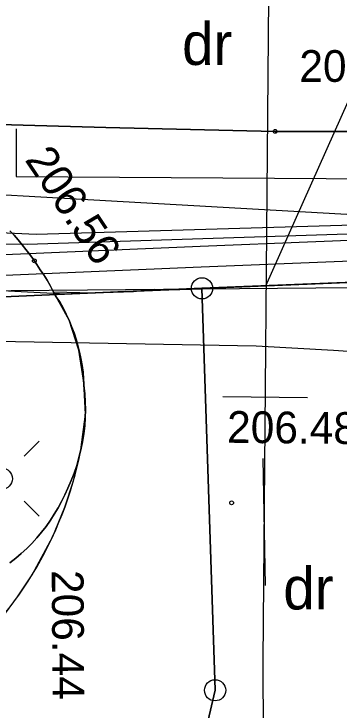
# Model space of a CAD drawing. Extents: x 6512606 to 6513006, y 6022524 to 6022728.
# Drawn here: x 6512731.32 to 6512739, y 6022662.97 to 6022679.43 of the extents above; entities that cross this region are included whole.
import ezdxf

# ---------------------------------------------------------------- set-up
doc = ezdxf.new("R2010")
doc.units = 0
for name, color, linetype in [('202-punkt graniczny', 7, 'Continuous'), ('210-oznaczenie konturu użytku gruntowego', 7, 'Continuous'), ('216-obręb ewidencyjny', 7, 'Continuous'), ('218-kontur użytku gruntowego', 7, 'Continuous'), ('219-działka ewidencyjna', 7, 'Continuous'), ('4', 7, 'Continuous'), ('chodnik (powierzchnia)', 7, 'Continuous'), ('Default', 7, 'Continuous'), ('jezdnia (powierzchnia)', 7, 'Continuous'), ('kolor_kostka_bet', 7, 'Continuous'), ('krawężnik (linia)', 7, 'Continuous'), ('latarnia (punkt)', 7, 'Continuous'), ('Level 60', 7, 'Continuous'), ('maxp_kan_deszczowa', 7, 'Continuous'), ('maxp_kraw_nawierzchni', 7, 'Continuous'), ('maxp_opisy', 7, 'Continuous'), ('maxp_opornik', 7, 'Continuous'), ('maxp_os', 7, 'Continuous'), ('maxp_ramka_2', 7, 'Continuous'), ('przewód elektroenergetyczny (linia)', 7, 'Continuous'), ('przewód elektroenergetyczny niskiego napięcia (linia)', 7, 'Continuous'), ('przewód kanalizacyjny (linia)', 7, 'Continuous'), ('przewód wodociągowy (linia)', 7, 'Continuous'), ('punkt wysokościowy sztuczny', 7, 'Continuous'), ('punkt wysokościowy sztuczny-Atr2', 7, 'Continuous')]:
    doc.layers.add(name, color=color, linetype=linetype)

# ---------------------------------------------------------------- blocks, each defined once
blk = doc.blocks.new('202')
at = {"layer": 'Default'}
blk.add_circle((0, 0), 2.5, dxfattribs=at)
blk = doc.blocks.new('PW02')
at = {"layer": 'Default'}
blk.add_circle((0, 0), 0.45, dxfattribs=at)
blk = doc.blocks.new('SM01')
at = {"layer": 'Default'}
for p, q in [((-5.3, 5.31), (-8.83, 8.84)), ((5.31, 5.31), (8.84, 8.84)), ((-5.3, -5.3), (-8.83, -8.83)), ((5.31, -5.3), (8.84, -8.83))]:
    blk.add_line(p, q, dxfattribs=at)
blk.add_circle((0, 0), 2.5, dxfattribs=at)

msp = doc.modelspace()

# ---------------------------------------------------------------- linework, layer by layer
at = {"layer": '216-obręb ewidencyjny'}
for points in [[(6512688.62, 6022674.91), (6512702.58, 6022674.18), (6512725.78, 6022672.95), (6512730.35, 6022672.71), (6512735.76, 6022672.94), (6512745.51, 6022673.33), (6512754.87, 6022673.72), (6512768.24, 6022674.27), (6512785.56, 6022674.74), (6512790.49, 6022674.74), (6512796.96, 6022674.74), (6512801.96, 6022670.34), (6512828.67, 6022670.98), (6512833.61, 6022675.02), (6512836.69, 6022675.17), (6512851.94, 6022675.93)], [(6512852.25, 6022608.25), (6512838.47, 6022634.29), (6512825.37, 6022649.66), (6512810.18, 6022663.28), (6512801.96, 6022670.34), (6512796.96, 6022674.74), (6512790.49, 6022674.74), (6512785.56, 6022674.74), (6512768.24, 6022674.27), (6512754.87, 6022673.72), (6512745.51, 6022673.33), (6512735.76, 6022672.94), (6512730.35, 6022672.71), (6512725.78, 6022672.95), (6512702.575, 6022674.177)]]:
    msp.add_lwpolyline(points, dxfattribs=at)
at = {"layer": '218-kontur użytku gruntowego'}
for points in [[(6512745.51, 6022673.33), (6512735.76, 6022672.94)], [(6512735.76, 6022672.94), (6512745.51, 6022673.33)], [(6512735.76, 6022672.94), (6512730.35, 6022672.71)], [(6512730.35, 6022672.71), (6512735.76, 6022672.94)], [(6512735.76, 6022672.94), (6512736.07, 6022663.44)], [(6512736.07, 6022663.44), (6512735.76, 6022672.94)], [(6512736.07, 6022663.44), (6512733.08, 6022650.62)], [(6512733.08, 6022650.62), (6512736.07, 6022663.44)]]:
    msp.add_lwpolyline(points, dxfattribs=at)
at = {"layer": '219-działka ewidencyjna'}
for points in [[(6512745.51, 6022673.33), (6512735.76, 6022672.94)], [(6512730.35, 6022672.71), (6512735.76, 6022672.94)], [(6512735.76, 6022672.94), (6512736.07, 6022663.44)], [(6512732.3, 6022647.29), (6512736.07, 6022663.44)]]:
    msp.add_lwpolyline(points, dxfattribs=at)
at = {"layer": '4'}
for points in [[(6512745.51, 6022673.33), (6512735.76, 6022672.94)], [(6512730.35, 6022672.71), (6512735.76, 6022672.94)], [(6512735.76, 6022672.94), (6512736.07, 6022663.44)], [(6512732.3, 6022647.29), (6512736.07, 6022663.44)]]:
    msp.add_lwpolyline(points, dxfattribs=at)
at = {"layer": 'chodnik (powierzchnia)'}
msp.add_lwpolyline([(6512706.86, 6022674.18), (6512711.28, 6022673.92), (6512732.54, 6022672.81)], dxfattribs=at)
at = {"layer": 'jezdnia (powierzchnia)'}
for points in [[(6512707.08, 6022677.87), (6512714.85, 6022677.5), (6512727.62, 6022676.91), (6512733.49, 6022676.74), (6512737.49, 6022676.65), (6512740.34, 6022676.65), (6512746.78, 6022676.72), (6512757.48, 6022676.77)], [(6512738.82, 6022655.07), (6512739.53, 6022663.03), (6512739.77, 6022665.13), (6512739.93, 6022667.1), (6512740.11, 6022668.94), (6512740.34, 6022670.38), (6512740.56, 6022671.39), (6512740.91, 6022672.33), (6512741.4, 6022673.19), (6512742.34, 6022674.38), (6512743.16, 6022675.08), (6512743.97, 6022675.6), (6512744.85, 6022676.05), (6512745.8, 6022676.43), (6512746.78, 6022676.72), (6512740.34, 6022676.65), (6512737.49, 6022676.65), (6512733.49, 6022676.74), (6512727.62, 6022676.91)], [(6512731.22, 6022674.3), (6512731.32, 6022674.2), (6512731.42, 6022674.09), (6512731.51, 6022673.97), (6512731.6, 6022673.86), (6512731.69, 6022673.74), (6512731.78, 6022673.62), (6512731.86, 6022673.5), (6512731.94, 6022673.38), (6512732.02, 6022673.26), (6512732.1, 6022673.13), (6512732.17, 6022673.01), (6512732.24, 6022672.88), (6512732.31, 6022672.75), (6512732.4, 6022672.62), (6512732.48, 6022672.48), (6512732.55, 6022672.33), (6512732.62, 6022672.19), (6512732.68, 6022672.04), (6512732.74, 6022671.89), (6512732.79, 6022671.74), (6512732.83, 6022671.59), (6512732.87, 6022671.43), (6512732.9, 6022671.28), (6512732.93, 6022671.12), (6512732.95, 6022670.96), (6512732.96, 6022670.8), (6512732.97, 6022670.64), (6512732.99, 6022670.45), (6512733, 6022670.26), (6512733.01, 6022670.07), (6512733, 6022669.88), (6512732.99, 6022669.69), (6512732.97, 6022669.5), (6512732.94, 6022669.31), (6512732.9, 6022669.12), (6512732.85, 6022668.94), (6512732.8, 6022668.75), (6512732.74, 6022668.57), (6512732.67, 6022668.4), (6512732.59, 6022668.22), (6512732.52, 6022668.06), (6512732.44, 6022667.9), (6512732.36, 6022667.75), (6512732.27, 6022667.6), (6512732.18, 6022667.46), (6512732.08, 6022667.31), (6512731.97, 6022667.18), (6512731.86, 6022667.04), (6512731.74, 6022666.91), (6512731.62, 6022666.79), (6512731.49, 6022666.67), (6512731.36, 6022666.56), (6512731.22, 6022666.45)]]:
    msp.add_lwpolyline(points, dxfattribs=at)
at = {"layer": 'kolor_kostka_bet'}
msp.add_line((6512741.477, 6022673.169), (6512732.281, 6022672.792), dxfattribs=at)
msp.add_lwpolyline([(6512732.281, 6022672.792), (6512732.62, 6022672.19), (6512732.83, 6022671.59), (6512732.93, 6022671.12), (6512732.96, 6022670.8), (6512733.01, 6022670.07), (6512732.99, 6022669.69), (6512732.938, 6022669.31)], dxfattribs=at)
msp.add_arc((6512724.075, 6022670.874), 9, 309.667, 349.9939, dxfattribs=at)
at = {"layer": 'krawężnik (linia)'}
for points in [[(6512707.08, 6022677.87), (6512714.85, 6022677.5), (6512727.62, 6022676.91), (6512733.49, 6022676.74), (6512737.49, 6022676.65), (6512740.34, 6022676.65), (6512746.78, 6022676.72), (6512757.48, 6022676.77)], [(6512727.62, 6022676.91), (6512733.49, 6022676.74), (6512737.49, 6022676.65), (6512740.34, 6022676.65), (6512746.78, 6022676.72), (6512745.8, 6022676.43), (6512744.85, 6022676.05), (6512743.97, 6022675.6), (6512743.16, 6022675.08), (6512742.34, 6022674.38), (6512741.4, 6022673.19), (6512740.91, 6022672.33), (6512740.56, 6022671.39), (6512740.34, 6022670.38), (6512740.11, 6022668.94), (6512739.93, 6022667.1), (6512739.77, 6022665.13), (6512739.53, 6022663.03), (6512738.82, 6022655.07)], [(6512731.22, 6022666.45), (6512731.36, 6022666.56), (6512731.49, 6022666.67), (6512731.62, 6022666.79), (6512731.74, 6022666.91), (6512731.86, 6022667.04), (6512731.97, 6022667.18), (6512732.08, 6022667.31), (6512732.18, 6022667.46), (6512732.27, 6022667.6), (6512732.36, 6022667.75), (6512732.44, 6022667.9), (6512732.52, 6022668.06), (6512732.59, 6022668.22), (6512732.67, 6022668.4), (6512732.74, 6022668.57), (6512732.8, 6022668.75), (6512732.85, 6022668.94), (6512732.9, 6022669.12), (6512732.94, 6022669.31), (6512732.97, 6022669.5), (6512732.99, 6022669.69), (6512733, 6022669.88), (6512733.01, 6022670.07), (6512733, 6022670.26), (6512732.99, 6022670.45), (6512732.97, 6022670.64), (6512732.96, 6022670.8), (6512732.95, 6022670.96), (6512732.93, 6022671.12), (6512732.9, 6022671.28), (6512732.87, 6022671.43), (6512732.83, 6022671.59), (6512732.79, 6022671.74), (6512732.74, 6022671.89), (6512732.68, 6022672.04), (6512732.62, 6022672.19), (6512732.55, 6022672.33), (6512732.48, 6022672.48), (6512732.4, 6022672.62), (6512732.31, 6022672.75), (6512732.24, 6022672.88), (6512732.17, 6022673.01), (6512732.1, 6022673.13), (6512732.02, 6022673.26), (6512731.94, 6022673.38), (6512731.86, 6022673.5), (6512731.78, 6022673.62), (6512731.69, 6022673.74), (6512731.6, 6022673.86), (6512731.51, 6022673.97), (6512731.42, 6022674.09), (6512731.32, 6022674.2), (6512731.22, 6022674.3)]]:
    msp.add_lwpolyline(points, dxfattribs=at)
at = {"layer": 'Level 60'}
for points in [[(6512738.251, 6022670.355), (6512736.251, 6022670.372)], [(6512737.2, 6022668.918), (6512737.253, 6022665.918)]]:
    msp.add_lwpolyline(points, dxfattribs=at)
at = {"layer": 'maxp_kan_deszczowa'}
msp.add_lwpolyline([(6512731.035, 6022665.144), (6512731.405, 6022665.652), (6512731.748, 6022666.171), (6512732.233, 6022667.075), (6512732.52, 6022667.765), (6512732.726, 6022668.393), (6512732.9, 6022669.12), (6512733.005, 6022669.968), (6512732.965, 6022670.717), (6512732.853, 6022671.481), (6512732.62, 6022672.19), (6512732.252, 6022672.859), (6512733.193, 6022672.831), (6512734.145, 6022672.868), (6512734.647, 6022672.919), (6512734.965, 6022672.906), (6512735.513, 6022672.922), (6512735.51, 6022672.924), (6512736.576, 6022672.973), (6512737.272, 6022673), (6512743.067, 6022673.232)], dxfattribs=at)
at = {"layer": 'maxp_kraw_nawierzchni'}
msp.add_line((6512732.281, 6022672.792), (6512741.477, 6022673.169), dxfattribs=at)
at = {"layer": 'maxp_opisy'}
msp.add_lwpolyline([(6512737.272, 6022673), (6512753.512, 6022709.396), (6512783.273, 6022709.39)], dxfattribs=at)
at = {"layer": 'maxp_opornik'}
msp.add_lwpolyline([(6512732.31, 6022672.75), (6512732.62, 6022672.19), (6512732.83, 6022671.59), (6512732.93, 6022671.12), (6512732.96, 6022670.8), (6512733.01, 6022670.07), (6512732.99, 6022669.69), (6512732.94, 6022669.31)], dxfattribs=at)
msp.add_arc((6512724.075, 6022670.874), 9, 309.667, 349.9939, dxfattribs=at)
at = {"layer": 'maxp_os'}
msp.add_line((6512737.332, 6022680.363), (6512737.2, 6022664.135), dxfattribs=at)
msp.add_arc((6512787.199, 6022663.73), 50, 179.5356, 182.0758, dxfattribs=at)
at = {"layer": 'maxp_ramka_2'}
for points in [[(6512723.981, 6022674.046), (6512730.355, 6022673.711), (6512735.719, 6022673.939), (6512746.649, 6022674.376)], [(6512746.149, 6022673.856), (6512735.739, 6022673.44), (6512730.352, 6022673.211), (6512724.475, 6022673.519)]]:
    msp.add_lwpolyline(points, dxfattribs=at)
at = {"layer": 'przewód elektroenergetyczny (linia)'}
for points in [[(6512731.37, 6022676.71), (6512731.37, 6022675.58), (6512748.46, 6022675.47), (6512780.13, 6022675.56), (6512787.87, 6022675.5)], [(6512702.569, 6022673.878), (6512710.28, 6022673.25), (6512716.66, 6022675.97), (6512746.13, 6022674.3), (6512752.79, 6022674.32), (6512760.61, 6022675.35), (6512763.38, 6022676.06), (6512798.79, 6022676.04), (6512803.06, 6022673.02), (6512807.84, 6022668.96), (6512815.24, 6022662.53), (6512819.98, 6022657.77), (6512831.6, 6022645.79), (6512834.59, 6022642.25), (6512837.06, 6022638.75), (6512840.02, 6022634.13), (6512842.26, 6022630.04), (6512846.03, 6022621.35), (6512846.58, 6022618.9), (6512847.6, 6022616.23), (6512852.12, 6022605.09)], [(6512702.603, 6022675.567), (6512731.84, 6022674.22), (6512765.79, 6022675.22), (6512787.87, 6022675.5)]]:
    msp.add_lwpolyline(points, dxfattribs=at)
at = {"layer": 'przewód elektroenergetyczny niskiego napięcia (linia)'}
msp.add_lwpolyline([(6512719.56, 6022672.79), (6512751.03, 6022673.06)], dxfattribs=at)
at = {"layer": 'przewód kanalizacyjny (linia)'}
msp.add_lwpolyline([(6512716.83, 6022672.25), (6512720.83, 6022672.11), (6512730.47, 6022671.7), (6512737.04, 6022671.58), (6512738.87, 6022671.48), (6512744.52, 6022671.09), (6512750.15, 6022670.75), (6512752.63, 6022670.67), (6512753.2, 6022670.48)], dxfattribs=at)
at = {"layer": 'przewód wodociągowy (linia)'}
msp.add_lwpolyline([(6512702.579, 6022674.359), (6512731.63, 6022673.98), (6512765.81, 6022675.09), (6512780.05, 6022675.09), (6512787.64, 6022675.26)], dxfattribs=at)

# ---------------------------------------------------------------- block references
at = {"layer": '202-punkt graniczny', "xscale": 0.1, "yscale": 0.10000000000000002}
for p in [(6512735.76, 6022672.94), (6512736.07, 6022663.44)]:
    msp.add_blockref('202', p, dxfattribs=at)
at = {"layer": 'latarnia (punkt)', "xscale": 0.1, "yscale": 0.10000000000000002}
msp.add_blockref('SM01', (6512731.03, 6022668.44), dxfattribs=at)
at = {"layer": 'punkt wysokościowy sztuczny', "xscale": 0.1, "yscale": 0.10000000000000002}
for p in [(6512737.49, 6022676.65), (6512731.8, 6022673.59), (6512736.46, 6022667.87)]:
    msp.add_blockref('PW02', p, dxfattribs=at)

# ---------------------------------------------------------------- texts
at = {"layer": '210-oznaczenie konturu użytku gruntowego'}
for p in [(6512735.29, 6022678.22), (6512737.68, 6022665.35)]:
    msp.add_text('dr', height=1, dxfattribs=at).set_placement(p)
at = {"layer": 'punkt wysokościowy sztuczny-Atr2'}
msp.add_text('206.44', height=0.75, dxfattribs=at).set_placement((6512738.06, 6022677.82))
for s, rotation, p in [('206.56', 303.69, (6512731.56, 6022675.98)), ('206.48', 359.428, (6512736.35, 6022669.29)), ('206.44', 270.402, (6512732.21, 6022666.28))]:
    msp.add_text(s, height=0.75, rotation=rotation, dxfattribs=at).set_placement(p)

doc.saveas('drawing.dxf')
